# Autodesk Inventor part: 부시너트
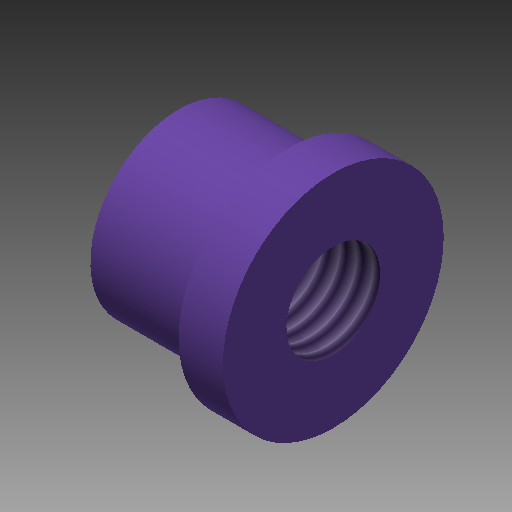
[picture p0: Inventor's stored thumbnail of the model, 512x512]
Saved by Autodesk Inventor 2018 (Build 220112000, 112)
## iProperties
Created: 2020-03
Part Number: 부시너트
Material: 스테인리스강
Document SubType Name: Modeling
Designer: mduedu
Density: 8.08 g/cm^3
Appearance: 보라색
Mass: 19.8459 g
Surface Area: 16.5062 cm^2
Volume: 2.45618 cm^3
Author: mduedu
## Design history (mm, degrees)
sketch "스케치1"
  geometry: L1 (0, 0)-(10, 0); L2 (10, 0)-(10, 8); L3 (10, 8)-(0, 8); L4 (0, 8)-(0, 0); L5 (10, 0)-(14, 0); L6 (14, 0)-(14, 10); L7 (14, 10)-(10, 10); L8 (10, 10)-(10, 0)
  constraints: 16 end point, 4 parallel, 2 horizontal, 2 perpendicular
  dimensions: "d0" = 14 distance between parallel lines of L6 L4; "d2" = 16 diameter of L3 L1; "d3" = 20 diameter of L7 L5; "d4" = 4 distance of L6.end L7.end
revolve "회전1" sketch "스케치1" stored, may be unused: angle "d5" = 90 deg
hole "구멍1" diameter "d8" = 8.5; stored, may be unused: countersink angle "d12" = 90 deg, drill point angle "d14" = 118 deg; dims "d9" = 6, "d10" = 4, "d11" = 2, "d13" = 8, "d15" = 10, "d16" = 10
sketch "스케치2"
  geometry: 3 further points
  constraints: 2 vertical alignment, 1 other
hole "구멍2" sketch "스케치2" at (0, -8) diameter "d17" = 2.459; stored, may be unused: countersink angle "d21" = 90 deg, drill point angle "d23" = 118 deg; dims "d18" = 5, "d19" = 4, "d20" = 2, "d22" = 7
node "솔리드1"
